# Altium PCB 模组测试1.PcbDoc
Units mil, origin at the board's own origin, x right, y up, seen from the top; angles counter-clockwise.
Board outline 2637.8 x 2031.5 mil, 2 copper layers (Top Layer, Bottom Layer); 29 components, 16 nets, 93 pads, 36 vias.
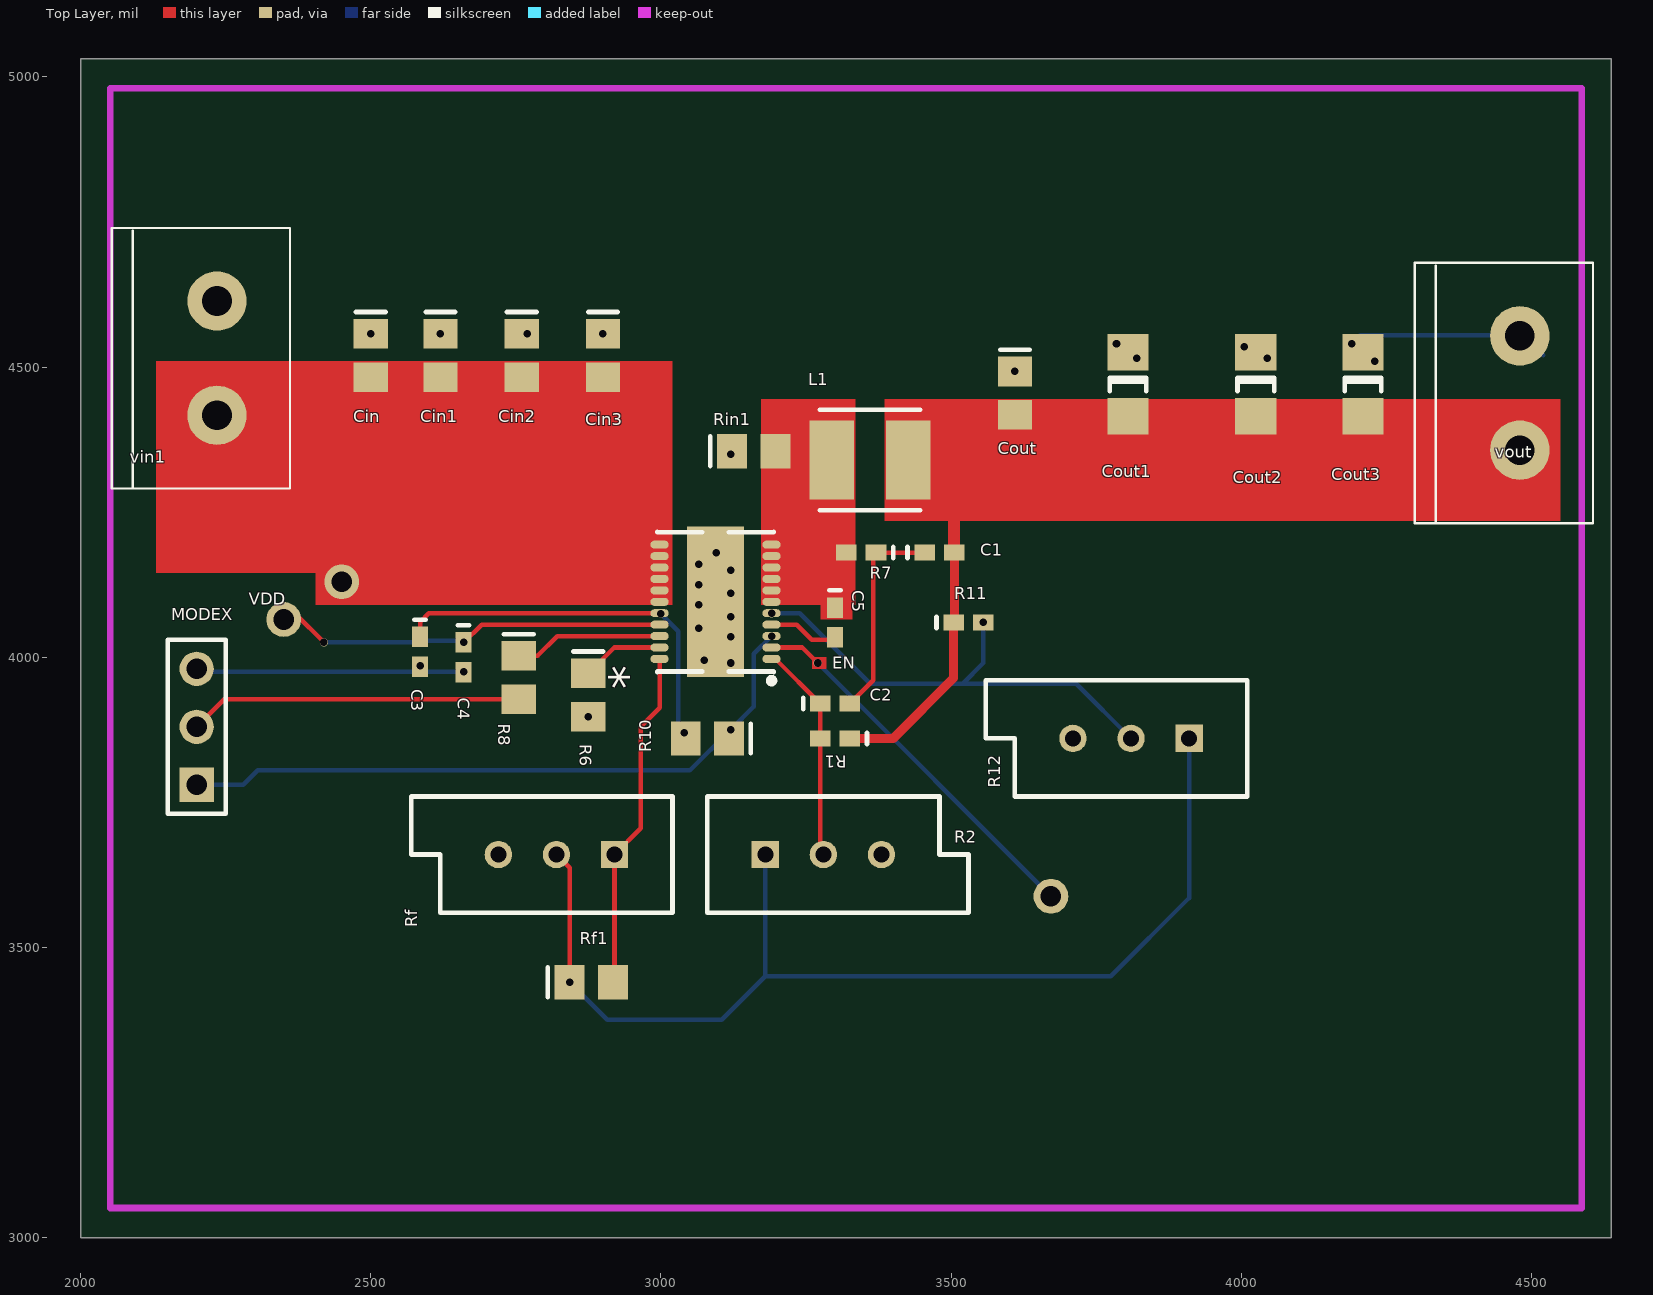
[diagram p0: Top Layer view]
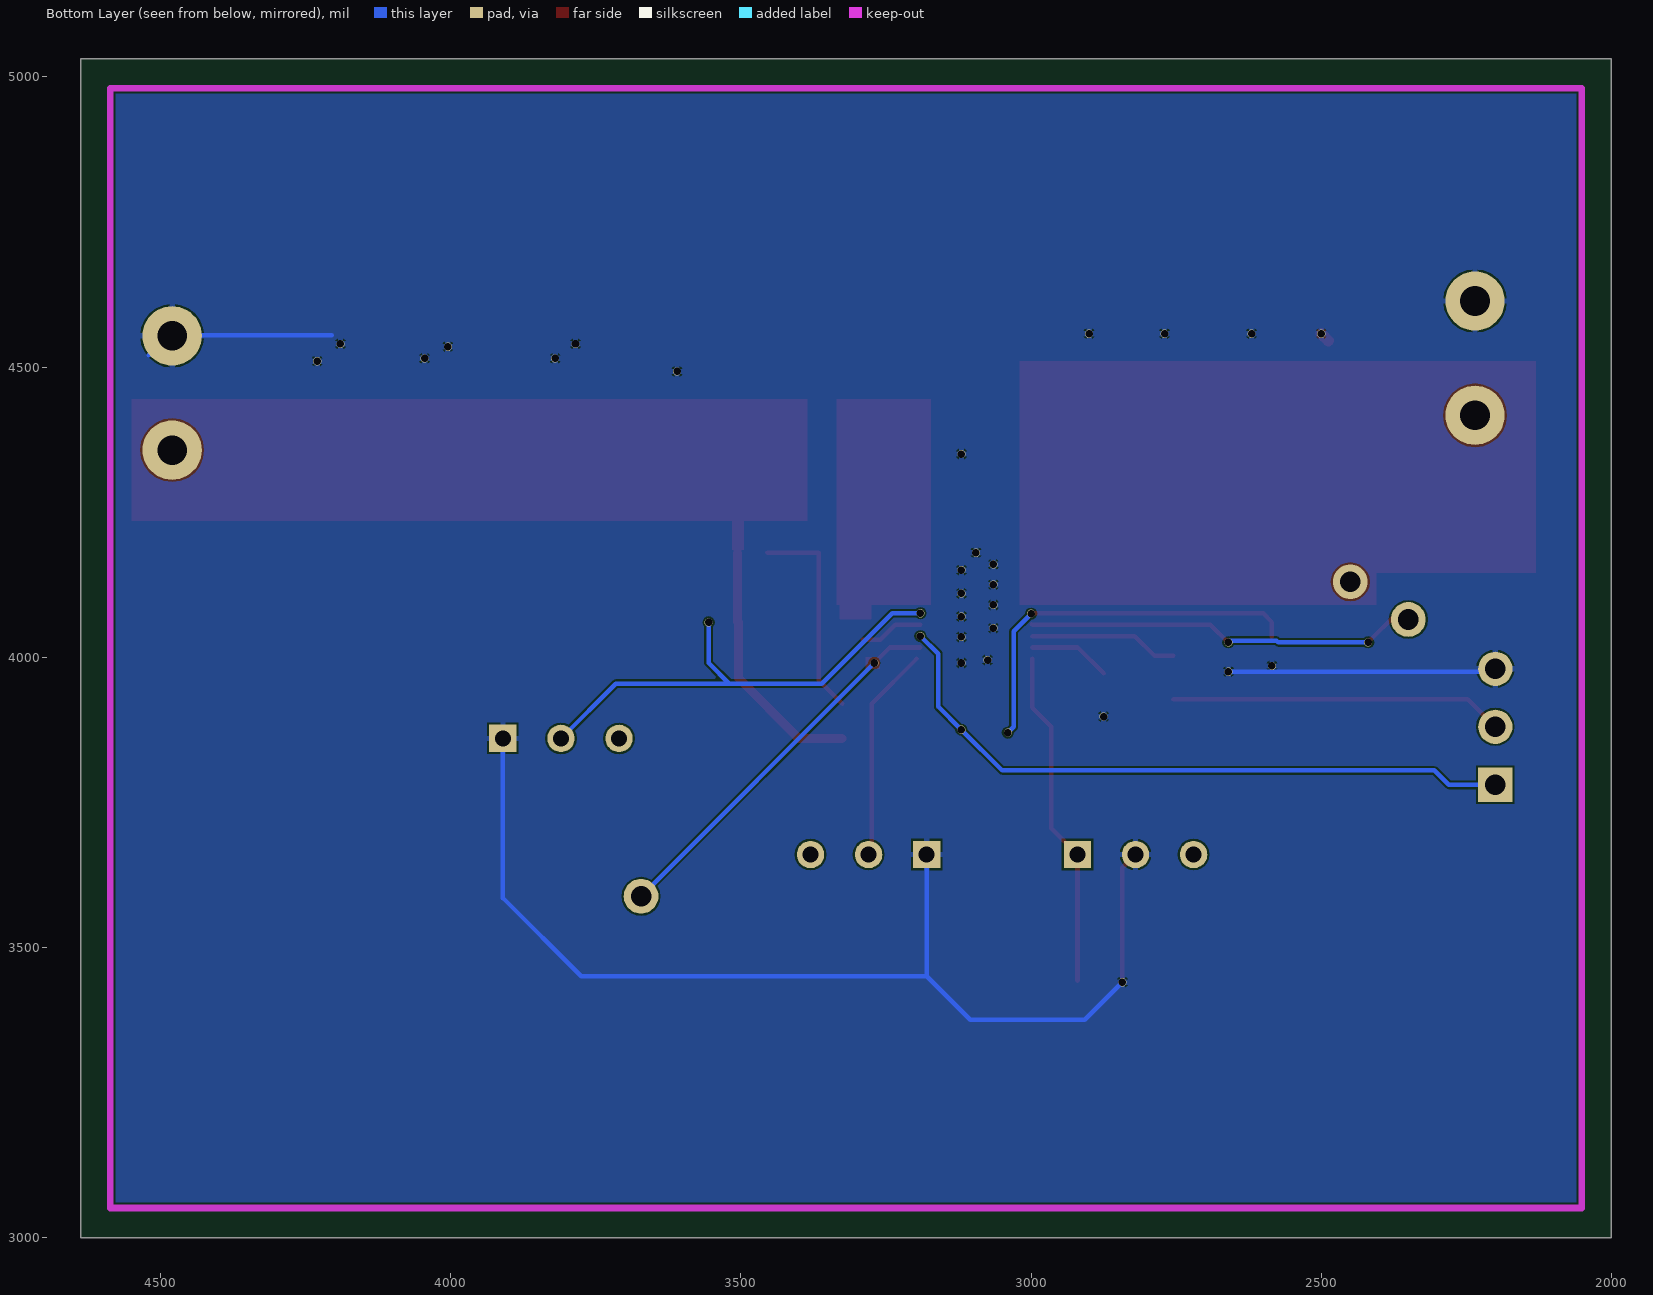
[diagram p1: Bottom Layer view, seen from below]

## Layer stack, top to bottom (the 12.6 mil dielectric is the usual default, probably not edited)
Top Layer: signal copper 1.4
Dielectric: dielectric 12.6, FR-4, Dk 4.8
Bottom Layer: signal copper 1.4

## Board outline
2000,3000 4637.8,3000 4637.8,5031.5 2000,5031.5

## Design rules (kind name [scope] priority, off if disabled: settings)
Clearance Clearance_1 [All] p1: gap=3.15
Clearance [All] p2: gap=7.87
PolygonConnect [All] p1: connectstyle=Relief reliefconductorwidth=10 reliefentries=4 polygonreliefangle="90 Angle"
RoutingVias [All] p1: holewidth=23.62 width=39.37 viastyle="Through Hole" minholewidth=28 minwidth=50 maxholewidth=28 maxwidth=50
SilkscreenOverComponentPads [All] p1: minsilkscreentomaskgap=10
SolderMaskExpansion [All] p1: expansion=4
Width Width_1 [InNet('NetC1_2')] p1: maxlimit=15.75 minlimit=15.75 preferedwidth=15.75
Width [All] p2: maxlimit=7.87 minlimit=7.87 preferedwidth=7.87
27 further rules are at their usual default settings.

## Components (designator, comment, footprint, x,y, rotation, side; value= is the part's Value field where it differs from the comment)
* "TPS53319" QFN0P601X500X150-22N 3480,4560 r90 top
C1 "Cap" 0402 3480,4180 r0 top
C2 "Cap" 0402 3300,3920 r0 top
C3 "Cap" 0402 2585,4009.41 r270 top
C4 "Cap" 0402 2660,4000 r270 top
C5 "Cap" 0402 3300,4060 r270 top
Cin "Cap" 0805 2500,4520 r270 top
Cin1 "Cap" 0805 2620,4520 r270 top
Cin2 "Cap" 0805 2760,4520 r270 top
Cin3 "Cap" 0805 2900,4520 r270 top
Cout "Cap" 0805 3610,4455 r270 top
Cout1 "Cap" 1206 3805,4470 r270 top
Cout2 "Cap" 1206 4025,4470 r270 top
Cout3 "Cap" 1206 4210,4470 r270 top
L1 "Inductor" XEL4020 3360,4340 r0 top
MODEX "Header 3" HDR1X3 2200,3780 r90 top
R1 "Res2" 0402 3300,3860 r180 top
R2 "Res2" 滑动电阻器 3280,3660 r0 top
R6 "Res2" 0805 2755,3965 r270 top
R7 "Res2" 0402 3345,4180 r180 top
R8 "Res2" 0805 2875,3935 r270 top
R10 "Res2" 0805 3080,3860 r180 top
R11 "Res2" 0402 3530,4060 r0 top
R12 "Res2" 滑动电阻器 3810,3860 r180 top
Rf "Res2" 滑动电阻器 2820,3660 r180 top
Rf1 "Res2" 0805 2880,3440 r0 top
Rin1 "Res2" 0805 3160,4355 r0 top
vin1 "接线柱" 接线柱 2235,4220 r90 top
vout "接线柱" 接线柱 4480,4160 r90 top

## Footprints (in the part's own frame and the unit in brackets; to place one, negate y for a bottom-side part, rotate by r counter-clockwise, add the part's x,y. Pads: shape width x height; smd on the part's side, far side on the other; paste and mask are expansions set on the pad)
0402 [mm] "Chip Capacitor; Body 1.0 x 0.5 mm (LxW typ)"
  rect 0.9x0.7 smd: 1(-0.65,0) 2(0.65,0)
  silkscreen extent -1.4,-0.25 -1.4,0.25
0805 [mm] "Chip Capacitor; Body 2.0 x 1.2 mm (LxW typ)"
  rect 1.3x1.5 smd: 1(-0.95,0) 2(0.95,0)
  silkscreen extent -1.9,-0.65 -1.9,0.65
1206 [mm] "Chip Capacitor; Body 3.2 x 1.6 mm (LxW typ)"
  rect 1.6x1.8 smd: 1(-1.4,0) 2(1.4,0)
  silkscreen extent -0.3,-0.8 0.3,0.8
HDR1X3 [mm] "Connector; Header; 3 Position"
  rect 1.5x1.5 hole 0.9: 1(0,0)
  round 1.5 hole 0.9: 2(2.54,0) 3(5.08,0)
  silkscreen extent -1.27,-1.27 6.35,1.27
QFN0P601X500X150-22N [mm] "QFN, 22-Leads, Body 5.1x6.1mm (max), Pitch 0.50mm, Pitch1 0.00mm, IPC Medium Density"
  oval 0.35x0.8 smd: 1(-14.3,7.35) 2(-13.8,7.35) 3(-13.3,7.35) 4(-12.8,7.35) 5(-12.3,7.35) 6(-11.8,7.35) 7(-11.3,7.35) 8(-10.8,7.35) 9(-10.3,7.35) 10(-9.8,7.35) 11(-9.3,7.35) 12(-9.3,12.25) 13(-9.8,12.25) 14(-10.3,12.25) 15(-10.8,12.25) 16(-11.3,12.25) 17(-11.8,12.25) 18(-12.3,12.25) 19(-12.8,12.25) 20(-13.3,12.25) 21(-13.8,12.25) 22(-14.3,12.25)
  rect 3.6x2.5 smd: 23(-13.3,9.8) 23(-10.3,9.8)
  rect 3.2x0 smd: 24(-13.4,9.8) 28(-10.2,9.8)
  rect 0x3.2 smd: 25(-11.8,11.4) 26(-11.8,11.4) 29(-11.8,8.2) 30(-11.8,8.2)
  silkscreen extent -15.37,7.22 -8.73,12.35, body extent -14.85,7.25 -8.75,12.35, height 1.5
XEL4020 [mm] "Molded Capacitor, 2-Leads, Body 4.0x4.0mm, IPC Medium Density"
  rect 1.95x3.45 smd: 1(-1.675,0) 2(1.675,0)
  silkscreen extent -2.2,-2.2 2.2,2.2, body extent -2.15,-2.15 2.15,2.15, height 2.1
接线柱 [mm]
  round 2.6 hole 1.3 paste+0.254: 1(5,0) 2(10,0)
  silkscreen extent 1.8,-3.2 13.2,4.6
滑动电阻器 [mm] "Variable Resistor, Thru-Hole; 3 Leads"
  rect 1.2x1.2 hole 0.7: 1(-2.54,0)
  round 1.2 hole 0.7: 2(0,0) 3(2.54,0)
  silkscreen extent -5.08,-2.54 6.35,2.54

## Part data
C1 C2 C3 C4 C5 Cin Cin1 Cin2 Cin3 Cout Cout1 Cout2 Cout3: "Capacitor"
MODEX: "Header, 3-Pin"
R1 R2 R6 R7 R8 R10 R11 R12 Rf Rf1 Rin1: "Resistor"

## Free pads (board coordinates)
  round 60 hole 35.4: 0(2350,4065) 0(2450,4130) 0(3672.04,3587.96)

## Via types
v1: diameter 14, hole 13, Top Layer to Bottom Layer, 36 vias

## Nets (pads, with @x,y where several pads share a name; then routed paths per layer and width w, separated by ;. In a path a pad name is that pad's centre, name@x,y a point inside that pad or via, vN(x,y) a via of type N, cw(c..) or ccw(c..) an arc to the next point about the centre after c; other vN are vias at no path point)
EN: *.2 pad.0@3672.04,3587.96 | length 660.1
  Top Layer w7.87: *.2 3243.31,4016.69 v1(3270,3990)
  Bottom Layer w7.87: v1(3270,3990) pad.0@3672.82,3587.18
GND: *.23 C3.2 C4.2 Cin1.1 Cin2.1 Cin3.1 Cin.1 Cout1.1 Cout2.1 Cout3.1 Cout.1 MODEX.3 R2.1 R8.2 R12.1 Rf1.1 Rf.2 Rin1.1 vin1.2 vout.2 | length 2709.8
  Top Layer w7.87: Rf.2 2842.6,3637.4 v1(2842.6,3440)
  Top Layer w19.68: Cin.1@2487.6,4545 v1(2500,4557.4)
  Bottom Layer w7.87: MODEX.3 2205,3975 v1(2660,3975) ; v1(2842.6,3440) 2907.6,3375 3105,3375 3180,3450 ; R2.1 3180,3450 ; R12.1 3910,3585 3775,3450 3180,3450 ; 4205,4555 4255,4555 ; 4250,4555 4255,4555 ; 4520,4520 4485,4555 4255,4555
  other v1: 2875,3897.6 2585,3985 3120,3990 3075,3995 3120,4035 3065,4050 3120,4070 3065,4090 3120,4110 3065,4125 3120,4150 3065,4160 3095,4180 3120,4350 3610,4492.4 4230,4510 3820,4515 4045,4515 4005,4535 3785,4540 4190,4540 2620,4557.4 2770,4557.4 2900,4557.4
MODE: MODEX.2 R6.2 | length 574.7
  Top Layer w7.87: MODEX.2 2247.6,3927.6 R6.2
Net*_1: *.1 C2.1 R1.2 R2.2 | length 371.2
  Top Layer w7.87: *.1@3197.4,3997.01 C2.1 3274.41,3665.59 R2.2
Net*_4: *.4 C5.2 | length 110.2
  Top Layer w7.87: *.4 3233.94,4056.06 3260,4030 C5.2@3290,4030
Net*_5: *.5 R11.2 R12.2 | length 829.1
  Bottom Layer w7.87: v1(3190.63,4075.75) 3239.25,4075.75 3360.59,3954.41 3520,3954.41 ; v1(3555.59,4060) 3555.59,3990 3520,3954.41 ; R12.2 3715.59,3954.41 3520,3954.41
Net*_6: *.6 *.7 *.8 *.9 *.10 *.11 C5.1 L1.1 R7.2 Rin1.2 | length 42.4
  Top Layer w7.87: *.10 *.11 3190.63,4216.57
Net*_12: *.12 *.13 *.14 *.15 *.16 *.17 Cin1.2 Cin2.2 Cin3.2 Cin.2 pad.0@2450,4130 vin1.1 | length 932.4
  Top Layer w7.87: vin1.1 2438.15,4416.85 ; Cin.2 Cin1.2 Cin2.2 Cin3.2 2997.72,4384.88 *.12
Net*_20: *.20 R6.1 | length 256.8
  Top Layer w7.87: R6.1 2787.4,4002.4 2821.38,4036.38 *.20
Net*_21: *.21 R8.1 | length 141.1
  Top Layer w7.87: R8.1 2919.29,4016.69 *.21
Net*_22: *.22 Rf1.2 Rf.1 | length 586.6
  Top Layer w7.87: Rf1.2@2920,3442.6 Rf.1 2965,3705 2965,3880 2997.72,3912.72 *.22
NetC1_1: C1.1 C2.2 R7.1 | length 365.4
  Top Layer w7.87: C2.2 3365.59,3960 3365.59,4180 C1.1
NetC1_2: C1.2 Cout1.2 Cout2.2 Cout3.2 Cout.2 L1.2 R1.1 R11.1 vout.1 | length 880.6
  Top Layer w7.87: Cout.2@3610,4402.6 Cout.2@3610.63,4403.23
  Top Layer w15.75: R1.1 3400,3860 3504.41,3964.41 R11.1 ; R11.1@3505.59,4061.18 C1.2 ; Cout2.2@4060,4403.23 4280,4403.23 4503.23,4403.23
PGOOD: *.3 MODEX.1 R10.1 | length 1150
  Bottom Layer w7.87: MODEX.1 2280,3780 2305,3805 3050,3805 v1(3120,3875) 3160,3915 3160,4005.75 v1(3190.63,4036.38)
VDD: *.19 C4.1 pad.0@2350,4065 | length 664.6
  Top Layer w7.87: pad.0@2370,4075 v1(2419.41,4025.59) ; v1(2660,4025.59) 2660.59,4025.59 2691.06,4056.06 *.19 *.19@2998.7,4057.05
  Bottom Layer w7.87: v1(2419.41,4025.59) 2574.18,4025.59 2577.09,4028.5 2657.09,4028.5 v1(2660,4025.59)
VREG: *.18 C3.1 R10.2 | length 671
  Top Layer w7.87: C3.1 2585,4060.59 2600.16,4075.75 2655,4075.75 ; 2650.16,4075.75 2655,4075.75 ; *.18 2655,4075.75
  Bottom Layer w7.87: v1(3000,4075) 3030,4045 3030,3880 v1(3040,3870)
pads on no net: *.24 *.25 *.26 *.28 *.29 *.30 R2.3 R12.3 Rf.3

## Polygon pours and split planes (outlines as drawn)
GND on Bottom Layer "Bottom Layer-No Net" (solid, pour order 1000): 2051.18,4980.32 2051.18,3051.18 4586.61,3051.18 4586.61,4975 4586.61,4980.32

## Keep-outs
Keep-Out Layer:
  lines w11.81: 2051.18,3051.18 4586.61,3051.18 4586.61,4980.32 2051.18,4980.32 2051.18,3051.18

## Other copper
Top Layer:
  rectangle net Net*_12: 2130,4145 2485,4510
  rectangle net Net*_12: 2405,4090 3020,4510
  rectangle net Net*_6: 3172.17,4090 3335,4445
  rectangle net Net*_6: 3275,4065 3330,4115
  rectangle net NetC1_2: 3385,4235 4550,4445
  rectangle net EN: 3260,3980 3285,4000
  rectangle net NetC1_2: 3495,4185 3515,4265

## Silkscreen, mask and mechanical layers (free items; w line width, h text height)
Top Overlay:
  text "VDD" at 2290,4090 h20.63
  text "EN" at 3295,3980 h20.63
Drill Drawing:
  text ".LEGEND" at 4837.8,3200 h60
  text "Drill Drawing." at 4837.8,3100 h60

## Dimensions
2051.18,3051.18 to 4586.61,3051.18 on Mechanical 1
2051.18,3051.18 to 2051.18,4980.32 on Mechanical 1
